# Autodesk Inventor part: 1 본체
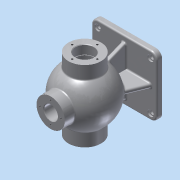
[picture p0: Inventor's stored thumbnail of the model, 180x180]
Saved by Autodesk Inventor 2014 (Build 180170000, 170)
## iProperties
Created: 2017-01
Part Number: 1 본체
Material: Aluminum 6061
Document SubType Name: Modeling
Designer: ksu
Density: 2.71 g/cm^3
Appearance: Aluminum - Flat
Author: ksu
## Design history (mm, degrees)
sketch "Sketch1"
  geometry: L1 (-62.5, -57.5)-(62.5, -57.5); L2 (62.5, -57.5)-(62.5, 57.5); L3 (62.5, 57.5)-(-62.5, 57.5); L4 (-62.5, 57.5)-(-62.5, -57.5); L5 (-62.5, -57.5)-(62.5, 57.5); L6 (62.5, -57.5)-(-62.5, 57.5); 1 further point
  constraints: 12 end point, 2 midpoint, 2 parallel, 1 horizontal, 1 perpendicular
  dimensions: "d0" = 125 distance of L2.end L3.end; "d1" = 115 distance of L1.end L2.end
extrude "Extrusion1" new body sketch "Sketch1" distance "d2" = 10; taper "d3" = 0 deg
workplane "Work Plane1"
sketch "Sketch2"
  geometry: L1 (8.66, 52.288)-(-8.66, -52.288); A1 r 53 centre (0, 0) between (8.66, 52.288) and (-8.66, -52.288); 1 further point
  constraints: 2 end point, 2 point on circle, 1 centre point, 1 coincident, 1 midpoint
  dimensions: "d5" = 106 diameter of A1
revolve "Revolution1" sketch "Sketch2" stored, may be unused: angle "d6" = 90 deg
workplane "Work Plane2"
sketch "Sketch5"
  geometry: L1 (-62.5, 0)-(62.5, 0) reference; L2 (88.536, 85)-(-90.621, 85); L3 (0, 0)-(0, 119.622); C1 r 31 at (0, 85)
  constraints: 4 end point, 2 point on line, 1 centre point, 1 parallel, 1 perpendicular
  dimensions: "d18" = 85 distance between parallel lines of L1 L2; "d19" = 62 diameter of C1
extrude "Extrusion3" join sketch "Sketch5" distance "d20" = 136; taper "d21" = 0 deg
workplane "Work Plane3"
sketch "Sketch6"
  geometry: C1 r 27 at (0, 0); 1 further point
  constraints: 1 centre point, 1 coincident
  dimensions: "d23" = 54 diameter of C1
extrude "Extrusion4" join sketch "Sketch6" distance "d24" = 65; taper "d25" = 0 deg
sketch "Sketch8"
  geometry: L1 (-57.5, 0)-(-57.5, 10) reference; L2 (-57.5, 10)-(57.5, 10) reference; L3 (-42.988, 54)-(-68, 54) reference; L4 (-68, 54)-(-68, 116) reference; L5 (-68, 116)-(-42.988, 116) reference; L6 (-27, 130.607)-(-27, 150) reference; L7 (-27, 150)-(27, 150) reference; L8 (27, 150)-(27, 130.607) reference; L9 (42.988, 116)-(68, 116) reference; L10 (68, 116)-(68, 54) reference; L11 (68, 54)-(42.988, 54) reference; L12 (57.5, 10)-(57.5, 0) reference; L13 (57.5, 0)-(-57.5, 0) reference; L14 (0, 85)-(-68, 85); L15 (0, 85)-(68, 85); L16 (52, 103.5)-(50.25, 103.5); L17 (52, 102.5)-(68, 102.5); L18 (50.25, 103.5)-(50.25, 102.5); L19 (52, 103.5)-(52, 102.5); L20 (68, 85.456)-(68, 102.5); L21 (68, 102.5)-(68, 85); L22 (68, 85)-(68, 102.5); L23 (-68, 102.5)-(-68, 85); L24 (-68, 102.5)-(-68, 85); L25 (68, 102.5)-(68, 85.456); L26 (68, 102.5)-(68, 85); L27 (68, 102.5)-(70.625, 102.5); L28 (70.625, 102.5)-(70.625, 85); L29 (70.625, 85)-(68, 85); L30 (-68, 102.5)-(-39.278, 102.5); L31 (39.278, 102.5)-(50.25, 102.5); A1 r 53 centre (0, 85) between (0, 32) and (42.988, 54) reference; A2 r 53 centre (0, 85) between (42.988, 116) and (27, 130.607) reference; A3 r 43 centre (0, 85) between (39.278, 102.5) and (-39.278, 102.5); A4 r 53 centre (0, 85) between (-27, 130.607) and (-42.988, 116) reference; A5 r 53 centre (0, 85) between (-42.988, 54) and (0, 32) reference; 1 further point
  constraints: 36 end point, 7 perpendicular, 4 collinear, 4 parallel, 3 point on line, 2 midpoint, 2 point on circle, 1 centre point, 1 coincident
  dimensions: "d26" = 86 diameter of A3
revolve "Revolution2" sketch "Sketch8" stored, may be unused: angle "d31" = 90 deg
sketch "Sketch9"
  geometry: C1 r 27 at (0, 0) reference; 1 further point
  constraints: 1 coincident
hole "Hole1" sketch "Sketch9" at (0, 0) diameter "d32" = 26; stored, may be unused: countersink angle "d36" = 90 deg, drill point angle "d38" = 118 deg; dims "d33" = 6, "d34" = 4, "d35" = 2, "d37" = 50
sketch "Sketch12"
  geometry: L1 (62.5, 0)-(-62.5, 0) reference; L2 (-62.5, 0)-(-62.5, 10) reference; L3 (62.5, 10)-(-62.5, 10) reference; L4 (62.5, 0)-(62.5, 10) reference; L5 (13, 125.988)-(-13, 125.988) reference; L6 (52.5, 10)-(36.656, 49.214); L7 (-52.5, 10)-(-36.656, 49.214); L8 (0, 32)-(0, 33.772); L9 (-52.5, 10)-(52.5, 10); C1 r 17.5 at (0, 85) reference; C2 r 17.5 at (0, 85) reference; A1 r 53 centre (0, 85) between (-27, 130.607) and (27, 130.607) reference; A2 r 51.228 centre (0, 85) between (-36.656, 49.214) and (36.656, 49.214); 1 further point
  constraints: 8 end point, 4 point on circle, 1 centre point, 1 coincident
  dimensions: "d49" = 22 deg angle of L4 L6
extrude "Extrusion5" join sketch "Sketch12" stored distance "d50" = 8; taper "d51" = 0 deg
sketch "Sketch13"
  geometry: L1 (42.988, 116)-(68, 116) reference; L2 (68, 116)-(68, 102.5) reference; L3 (68, 102.5)-(52, 102.5) reference; L4 (52, 102.5)-(52, 103.5) reference; L5 (52, 103.5)-(50.25, 103.5) reference; L6 (50.25, 103.5)-(50.25, 102.5) reference; L7 (50.25, 102.5)-(39.278, 102.5) reference; L8 (13, 125.988)-(13, 150) reference; L9 (13, 150)-(27, 150) reference; L10 (27, 150)-(27, 130.607) reference; L11 (-68, 116)-(-42.988, 116) reference; L12 (-27, 130.607)-(-27, 150) reference; L13 (-27, 150)-(-13, 150) reference; L14 (-13, 150)-(-13, 125.988) reference; L15 (-39.278, 102.5)-(-68, 102.5) reference; L16 (-68, 102.5)-(-68, 116) reference; L17 (-42.988, 54)-(-68, 54) reference; L18 (-68, 54)-(-68, 67.5) reference; L19 (-68, 67.5)-(-39.278, 67.5) reference; L20 (39.278, 67.5)-(50.25, 67.5) reference; L21 (50.25, 67.5)-(50.25, 66.5) reference; L22 (50.25, 66.5)-(52, 66.5) reference; L23 (52, 66.5)-(52, 67.5) reference; L24 (52, 67.5)-(68, 67.5) reference; L25 (68, 67.5)-(68, 54) reference; L26 (68, 54)-(42.988, 54) reference; L27 (4, 32.151)-(4, 10) reference; L28 (4, 10)-(57.5, 10) reference; L29 (57.5, 10)-(57.5, 0) reference; L30 (57.5, 0)-(-57.5, 0) reference; L31 (-57.5, 0)-(-57.5, 10) reference; L32 (-57.5, 10)-(-4, 10) reference; L33 (-4, 10)-(-4, 32.151) reference; L34 (47.5, 10)-(47.5, 0); L35 (47.5, 10)-(32.63, 46.805); L36 (-47.5, 10)-(-32.63, 46.805); L37 (-47.5, 10)-(47.5, 10); A1 r 43 centre (0, 85) between (39.278, 102.5) and (13, 125.988) reference; A2 r 53 centre (0, 85) between (42.988, 116) and (27, 130.607) reference; A3 r 53 centre (0, 85) between (-27, 130.607) and (-42.988, 116) reference; A4 r 43 centre (0, 85) between (-13, 125.988) and (-39.278, 102.5) reference; A5 r 43 centre (0, 85) between (-39.278, 67.5) and (39.278, 67.5) reference; A6 r 53 centre (0, 85) between (4, 32.151) and (42.988, 54) reference; A7 r 53 centre (0, 85) between (-42.988, 54) and (-4, 32.151) reference; A8 r 50.235 centre (0, 85) between (-32.63, 46.805) and (32.63, 46.805); 1 further point
  constraints: 10 end point, 2 point on circle, 1 centre point, 1 coincident, 1 parallel, 1 perpendicular
  dimensions: "d52" = 10 distance between parallel lines of L29 L34; "d53" = 22 deg angle of L29 L35
extrude "Extrusion6" join sketch "Sketch13" stored distance "d54" = 8; taper "d55" = 0 deg
sketch "Sketch14"
  geometry: C1 r 27 at (0, 0) reference; A1 r 20 centre (0, 0) between (0, 20) and (20, 0); 2 further points
  constraints: 4 point on circle, 1 centre point, 1 coincident
  dimensions: "d56" = 40 diameter of A1
hole "Hole2" sketch "Sketch14" at (20, 0), (0, 20), (-20, 0), (0, -20) diameter "d57" = 3.459; stored, may be unused: countersink angle "d61" = 90 deg, drill point angle "d63" = 118 deg; dims "d58" = 9, "d59" = 4, "d60" = 2, "d62" = 11
sketch "Sketch15"
  geometry: C1 r 31 at (0, 0) reference; A1 r 24 centre (0, 0) between (0, 24) and (24, 0); 3 further points
  constraints: 4 point on circle, 1 centre point, 1 coincident
  dimensions: "d64" = 48 diameter of A1
hole "Hole3" sketch "Sketch15" at (0, -24), (24, 0), (0, 24), (-24, 0) diameter "d65" = 3.459; stored, may be unused: countersink angle "d69" = 90 deg, drill point angle "d71" = 118 deg; dims "d66" = 16, "d67" = 4, "d68" = 2, "d70" = 19
sketch "Sketch16"
  geometry: C1 r 31 at (0, 0) reference; A1 r 22.5 centre (0, 0) between (0, 22.5) and (22.5, 0); 3 further points
  constraints: 4 point on circle, 1 centre point, 1 coincident
  dimensions: "d72" = 45 diameter of A1
hole "Hole4" sketch "Sketch16" at (0, -22.5), (22.5, 0), (0, 22.5), (-22.5, 0) diameter "d73" = 3.459; stored, may be unused: countersink angle "d77" = 90 deg, drill point angle "d79" = 118 deg; dims "d74" = 12, "d75" = 4, "d76" = 2, "d78" = 15
fillet "Fillet1" dims "d80" = 12
sketch "Sketch17"
  geometry: A1 r 12 centre (-50.5, 45.5) between (-50.5, 57.5) and (-62.5, 45.5) reference; A2 r 12 centre (-50.5, -45.5) between (-62.5, -45.5) and (-50.5, -57.5) reference; A3 r 12 centre (50.5, -45.5) between (50.5, -57.5) and (62.5, -45.5) reference; A4 r 12 centre (50.5, 45.5) between (62.5, 45.5) and (50.5, 57.5) reference; 5 further points
  constraints: 4 coincident
hole "Hole5" sketch "Sketch17" at (-50.5, 45.5), (50.5, 45.5), (-50.5, -45.5), (50.5, -45.5) diameter "d81" = 8; stored, may be unused: countersink angle "d85" = 90 deg, drill point angle "d87" = 118 deg; dims "d82" = 12, "d83" = 12, "d84" = 3, "d86" = 10
chamfer "Chamfer1" distance "d88" = 1; stored, may be unused: second distance "d89" = 2, angle "d90" = 45 deg
fillet "Fillet2" dims "d91" = 3
fillet "Fillet3" dims "d92" = 3
fillet "Fillet4" dims "d93" = 3
fillet "Fillet5" dims "d94" = 3
workplane "Work Plane5"
sketch "Sketch19"
  geometry: L1 (0, 0)-(0, 184.171); L2 (27, 150)-(27, 132.286) reference; L3 (-27, 150)-(27, 150) reference; L4 (35.897, 140)-(-32.574, 140); L5 (-20.739, 143.002)-(20.739, 143.002); L6 (20.739, 143.002)-(20.739, 136.998); L7 (20.739, 136.998)-(-20.739, 136.998); L8 (-20.739, 136.998)-(-20.739, 143.002); 1 further point
  constraints: 4 end point, 2 point on line, 1 parallel, 1 vertical, 2 other
  dimensions: "d100" = 10 distance between parallel lines of L3 L4
emboss "Emboss2" sketch "Sketch19" dims "d0" = 125, "d1" = 115, "d20" = 136, "d101" = 0.5, "d102" = 0
body "Solid1"
node "Projected Loop4"
node "Projected Loop5"
node "Project Cut Edges1"
node "Project Cut Edges2"
other parameters: "d4" = 85, "d11" = 4, "d12" = 4, "d13" = 4, "d14" = 4, "d17" = 68, "d27" = 17.5, "d28" = 16, "d29" = 18.5, "d30" = 1.75, "d41" = 106, "d45" = 106
